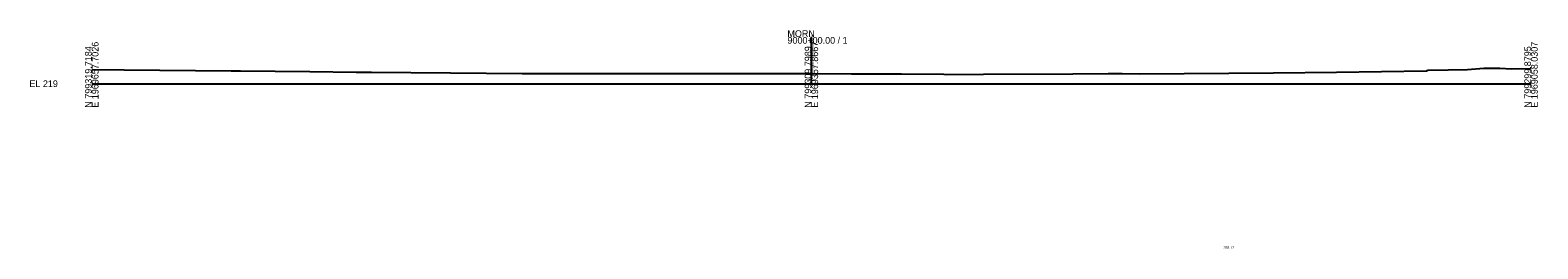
# Model space of a CAD drawing. Extents: x -26 to 1603, y -10 to 19642.
# Drawn here: x -26 to 603, y 431 to 522 of the extents above; entities that cross this region are included whole.
import ezdxf

# ---------------------------------------------------------------- set-up
doc = ezdxf.new("R2010")
doc.units = 0
for name, color, linetype in [('Default', 7, 'Continuous'), ('RD_GPK_XS_Cell', 7, 'Continuous'), ('RD_Sketch1', 7, 'Continuous'), ('RD_XS_ExGround', 7, 'Continuous'), ('RD_XS_TX_Elev_EX', 7, 'Continuous'), ('RD_XS_TX_Warning', 7, 'Continuous')]:
    doc.layers.add(name, color=color, linetype=linetype)

msp = doc.modelspace()

# ---------------------------------------------------------------- linework, layer by layer
at = {"layer": 'RD_GPK_XS_Cell'}
for p, q in [((300, 500), (300, 519.46)), ((0, 500), (300, 500)), ((300, 500), (600, 500))]:
    msp.add_line(p, q, dxfattribs=at)
at = {"layer": 'RD_XS_ExGround'}
msp.add_lwpolyline([(0, 505.89), (13.48, 505.76), (58.14, 505.35), (62.06, 505.3), (90.85, 505.08), (110.25, 504.87), (116.58, 504.8), (149.57, 504.53), (179.42, 504.24), (182.96, 504.24), (223.92, 504.19), (228.16, 504.19), (230.64, 504.19), (232.81, 504.22), (277.77, 504.28), (280.03, 504.28), (281.36, 504.27), (282.23, 504.27), (300, 504.19), (316.75, 504.12), (337.6, 504.04), (355.16, 503.94), (356.47, 503.88), (371.75, 503.94), (408.99, 504.12), (423.69, 504.21), (426.71, 504.23), (429.57, 504.18), (436.84, 504.17), (492.7, 504.54), (518.89, 504.74), (556.48, 505.36), (557, 505.62), (565.45, 505.72), (573.56, 505.89), (580.35, 506.46), (583.92, 506.49), (587.05, 506.45), (591.83, 506.19), (600, 506.34)], dxfattribs=at)

# ---------------------------------------------------------------- texts
at = {"layer": 'Default'}
msp.add_text('-', height=0.0001, dxfattribs=at).set_placement((0, 500))
at = {"layer": 'RD_GPK_XS_Cell'}
for s, p in [('MORN', (290, 519.46)), ('9000+00.00 / 1', (290, 516.66)), ('EL 219', (-26, 498.6))]:
    msp.add_text(s, height=2.8, dxfattribs=at).set_placement(p)
for s, p in [('N 799319.7184', (0, 490)), ('E 1969657.7026', (2.8, 490)), ('N 799309.7989', (300, 490)), ('E 1969357.8667', (302.8, 490)), ('N 799299.8795', (600, 490)), ('E 1969058.0307', (602.8, 490))]:
    msp.add_text(s, height=2.8, rotation=90, dxfattribs=at).set_placement(p)
at = {"layer": 'RD_Sketch1'}
msp.add_text('L_TP', height=0.1, dxfattribs=at).set_placement((244.28, 504.24))
at = {"layer": 'RD_XS_TX_Elev_EX'}
for s, height, p in [('223.19', 0.7, (298.89, 501.19)), ('288.17', 1.042, (471.81, 431.2))]:
    msp.add_text(s, height=height, dxfattribs=at).set_placement(p)
at = {"layer": 'RD_XS_TX_Warning'}
msp.add_text('Irregular Pavement Found', height=1, rotation=90, dxfattribs=at).set_placement((301, 504.2))

doc.saveas('drawing.dxf')
